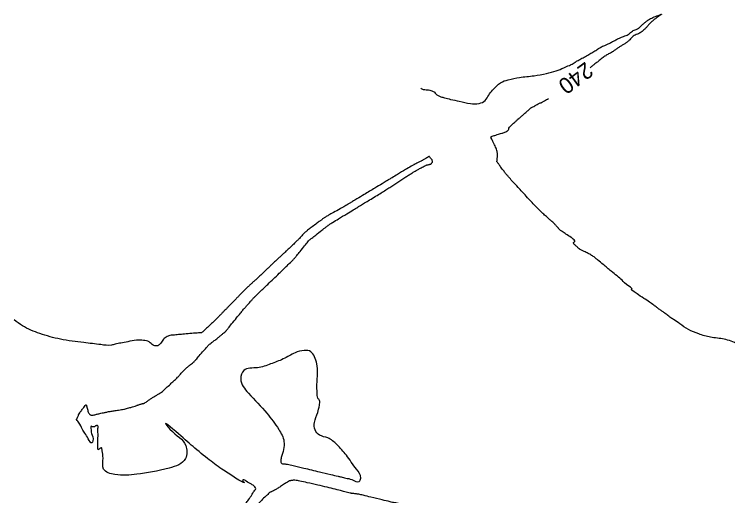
# Model space of a CAD drawing. Extents: x -478102 to -473059, y -1117705 to -1114104.
# Drawn here: x -477151.4 to -476973.3, y -1115105.7 to -1114985.6 of the extents above; entities that cross this region are included whole.
import ezdxf

# ---------------------------------------------------------------- set-up
doc = ezdxf.new("R2010")
doc.units = 0
for name, color, linetype in [('Vrstevnice_hlavni', 7, 'Continuous'), ('Vrstevnice_popis', 7, 'Continuous'), ('Vrstevnice_vedlejsi', 7, 'Continuous')]:
    doc.layers.add(name, color=color, linetype=linetype)

msp = doc.modelspace()

# ---------------------------------------------------------------- linework, layer by layer
at = {"layer": 'Vrstevnice_hlavni'}
for points in [[(-477049.979, -1115004.029), (-477049.673, -1115004.193), (-477048.26, -1115004.404), (-477047.204, -1115004.683), (-477046.505, -1115005.027), (-477046.164, -1115005.438), (-477045.639, -1115005.805), (-477044.929, -1115006.127), (-477044.034, -1115006.405), (-477042.508, -1115006.787), (-477040.351, -1115007.273), (-477037.562, -1115007.863), (-477035.407, -1115007.799), (-477033.886, -1115007.079), (-477033, -1115005.704), (-477032.062, -1115004.503), (-477031.073, -1115003.477), (-477030.034, -1115002.625), (-477028.119, -1115001.907), (-477025.328, -1115001.324), (-477021.663, -1115000.876), (-477018.599, -1115000.325), (-477016.138, -1114999.672), (-477014.278, -1114998.917), (-477012.873, -1114998.304), (-477011.923, -1114997.835), (-477011.428, -1114997.509), (-477010.705, -1114997.08), (-477009.754, -1114996.549), (-477008.574, -1114995.914), (-477007.491, -1114995.299), (-477006.505, -1114994.702), (-477005.616, -1114994.125), (-477004.874, -1114993.69), (-477004.28, -1114993.398), (-477003.833, -1114993.249), (-477003.188, -1114992.955), (-477002.345, -1114992.516), (-477001.305, -1114991.933), (-477000.403, -1114991.481), (-476999.64, -1114991.162), (-476999.016, -1114990.973), (-476998.464, -1114990.728), (-476997.985, -1114990.425), (-476997.579, -1114990.066), (-476997.143, -1114989.765), (-476996.676, -1114989.524), (-476996.178, -1114989.342), (-476995.627, -1114989.011), (-476995.023, -1114988.533), (-476994.365, -1114987.907), (-476993.741, -1114987.384), (-476993.153, -1114986.963), (-476992.599, -1114986.645), (-476992.009, -1114986.355), (-476991.383, -1114986.092), (-476990.719, -1114985.856), (-476990.255, -1114985.689), (-476989.991, -1114985.591), (-476989.925, -1114985.561), (-476989.901, -1114985.553), (-476989.919, -1114985.568), (-476989.977, -1114985.605), (-476990.02, -1114985.633), (-476990.048, -1114985.653), (-476990.061, -1114985.663), (-476990.326, -1114985.857), (-476990.841, -1114986.233), (-476991.608, -1114986.792), (-476992.308, -1114987.388), (-476992.94, -1114988.02), (-476993.504, -1114988.689), (-476994.025, -1114989.245), (-476994.503, -1114989.688), (-476994.937, -1114990.017), (-476995.402, -1114990.301), (-476995.899, -1114990.54), (-476996.428, -1114990.734), (-476996.92, -1114991.026), (-476997.375, -1114991.417), (-476997.795, -1114991.906), (-476998.298, -1114992.365), (-476998.884, -1114992.793), (-476999.553, -1114993.19), (-477000.214, -1114993.61), (-477000.867, -1114994.052), (-477001.512, -1114994.518), (-477002.106, -1114994.907), (-477002.649, -1114995.22), (-477003.142, -1114995.458), (-477003.814, -1114995.885), (-477004.665, -1114996.502)], [(-477004.665, -1114996.502), (-477005.695, -1114997.309), (-477006.489, -1114997.933), (-477007.047, -1114998.372), (-477007.691, -1114998.882)], [(-477017.894, -1115036.673), (-477018.831, -1115035.848), (-477019.673, -1115035.079), (-477020.422, -1115034.367), (-477021.076, -1115033.712), (-477022.168, -1115032.564), (-477023.697, -1115030.923), (-477025.662, -1115028.788), (-477027.122, -1115027.188), (-477028.074, -1115026.123), (-477028.52, -1115025.593), (-477029.034, -1115024.943), (-477029.617, -1115024.173), (-477030.269, -1115023.282), (-477030.708, -1115022.682), (-477030.934, -1115022.374), (-477030.946, -1115022.357), (-477030.928, -1115022.077), (-477030.878, -1115021.535), (-477030.797, -1115020.729), (-477030.934, -1115019.788), (-477031.286, -1115018.713), (-477031.856, -1115017.503), (-477032.238, -1115016.683), (-477032.433, -1115016.253), (-477032.44, -1115016.214), (-477032.443, -1115016.185), (-477032.441, -1115016.166), (-477032.435, -1115016.159), (-477032.431, -1115016.153), (-477032.428, -1115016.149), (-477032.426, -1115016.147), (-477032.373, -1115016.122), (-477032.267, -1115016.074), (-477032.11, -1115016.003), (-477031.64, -1115015.843), (-477030.858, -1115015.596), (-477029.763, -1115015.26), (-477028.959, -1115014.975), (-477028.444, -1115014.74), (-477028.219, -1115014.556), (-477028.06, -1115014.364), (-477027.968, -1115014.165), (-477027.943, -1115013.958), (-477027.674, -1115013.593), (-477027.161, -1115013.071), (-477026.405, -1115012.392), (-477025.889, -1115011.927), (-477025.616, -1115011.677), (-477025.583, -1115011.642), (-477025.534, -1115011.602), (-477025.469, -1115011.556), (-477025.387, -1115011.505), (-477025.033, -1115011.201), (-477024.407, -1115010.643), (-477023.509, -1115009.833), (-477022.858, -1115009.263), (-477022.455, -1115008.935), (-477022.299, -1115008.848), (-477021.991, -1115008.674), (-477021.533, -1115008.413), (-477020.923, -1115008.064), (-477020.468, -1115007.826), (-477020.167, -1115007.697), (-477020.021, -1115007.678), (-477019.883, -1115007.635), (-477019.754, -1115007.567), (-477019.633, -1115007.475), (-477019.398, -1115007.325), (-477019.047, -1115007.117), (-477018.115, -1115006.584)], [(-476873.251, -1115143.677), (-476873.507, -1115142.01), (-476873.554, -1115139.102), (-476873.522, -1115134.12), (-476873.41, -1115127.063), (-476873.808, -1115122.086), (-476874.717, -1115119.19), (-476876.136, -1115118.374), (-476877.354, -1115117.171), (-476878.371, -1115115.579), (-476879.185, -1115113.6), (-476882.364, -1115111.475), (-476887.908, -1115109.205), (-476895.815, -1115106.789), (-476902.242, -1115103.761), (-476907.186, -1115100.12), (-476910.649, -1115095.867), (-476913.66, -1115091.883), (-476916.218, -1115088.167), (-476918.324, -1115084.72), (-476919.725, -1115082.379), (-476920.421, -1115081.145), (-476920.412, -1115081.017), (-476920.426, -1115080.932), (-476920.462, -1115080.891), (-476920.521, -1115080.893), (-476920.576, -1115080.895), (-476920.627, -1115080.896), (-476920.674, -1115080.898), (-476921.736, -1115080.799), (-476923.814, -1115080.599), (-476926.907, -1115080.3), (-476932.302, -1115079.591), (-476940, -1115078.472), (-476950, -1115076.944), (-476957.876, -1115075.006), (-476963.629, -1115072.657), (-476967.259, -1115069.897), (-476970.802, -1115067.892), (-476974.259, -1115066.643), (-476977.631, -1115066.149), (-476980.601, -1115065.341), (-476983.17, -1115064.218), (-476985.338, -1115062.781), (-476986.878, -1115061.747), (-476987.79, -1115061.118), (-476988.074, -1115060.892), (-476988.478, -1115060.587), (-476989.003, -1115060.204), (-476989.648, -1115059.743), (-476990.332, -1115059.246), (-476991.055, -1115058.714), (-476991.817, -1115058.146), (-476992.891, -1115057.395), (-476994.277, -1115056.46), (-476995.976, -1115055.343), (-476997.039, -1115054.593), (-476997.464, -1115054.21), (-476997.254, -1115054.195), (-476998.009, -1115053.437), (-476999.729, -1115051.937), (-477002.416, -1115049.693), (-477004.444, -1115048.001), (-477005.814, -1115046.86), (-477006.527, -1115046.27), (-477007.324, -1115045.723), (-477008.206, -1115045.221), (-477009.173, -1115044.763), (-477009.833, -1115044.445), (-477010.186, -1115044.267), (-477010.232, -1115044.228), (-477010.318, -1115044.158), (-477010.443, -1115044.058), (-477010.608, -1115043.927), (-477010.866, -1115043.703), (-477011.219, -1115043.389), (-477011.666, -1115042.982), (-477011.859, -1115042.654), (-477011.796, -1115042.405), (-477011.479, -1115042.235), (-477011.695, -1115041.846), (-477012.445, -1115041.236), (-477013.729, -1115040.407), (-477014.642, -1115039.799), (-477015.184, -1115039.41), (-477015.355, -1115039.241), (-477015.476, -1115039.117), (-477015.545, -1115039.038), (-477015.564, -1115039.003), (-477015.672, -1115038.875), (-477015.869, -1115038.653), (-477016.157, -1115038.339), (-477016.405, -1115038.07), (-477016.615, -1115037.849), (-477016.786, -1115037.674), (-477017.213, -1115037.282), (-477017.894, -1115036.673)]]:
    msp.add_spline(points, degree=3, dxfattribs=at)
at = {"layer": 'Vrstevnice_vedlejsi'}
for points in [[(-477108.024, -1115073.453), (-477107.41, -1115072.982), (-477106.961, -1115072.629), (-477106.676, -1115072.395), (-477106.556, -1115072.278), (-477106.091, -1115071.757), (-477105.281, -1115070.832), (-477104.126, -1115069.502), (-477103.309, -1115068.574), (-477102.828, -1115068.046), (-477102.685, -1115067.92), (-477102.316, -1115067.626), (-477101.72, -1115067.165), (-477100.898, -1115066.537), (-477100.184, -1115065.97), (-477099.579, -1115065.464), (-477099.081, -1115065.02), (-477098.73, -1115064.701), (-477098.524, -1115064.509), (-477098.465, -1115064.444), (-477098.01, -1115063.889), (-477097.162, -1115062.844), (-477095.919, -1115061.311), (-477094.978, -1115060.158), (-477094.339, -1115059.385), (-477094.002, -1115058.992), (-477093.57, -1115058.494), (-477093.044, -1115057.889), (-477092.423, -1115057.178), (-477091.967, -1115056.663), (-477091.675, -1115056.343), (-477091.547, -1115056.218), (-477091.414, -1115056.093), (-477091.276, -1115055.968), (-477091.133, -1115055.843), (-477090.09, -1115054.841), (-477088.145, -1115052.963), (-477085.299, -1115050.207), (-477083.328, -1115048.299), (-477082.232, -1115047.238), (-477082.012, -1115047.025), (-477081.803, -1115046.81), (-477081.606, -1115046.593), (-477081.422, -1115046.376), (-477080.916, -1115045.76), (-477080.09, -1115044.745), (-477078.942, -1115043.332), (-477078.165, -1115042.381), (-477077.759, -1115041.889), (-477077.722, -1115041.859), (-477077.193, -1115041.444), (-477076.171, -1115040.644), (-477074.656, -1115039.459), (-477073.586, -1115038.623), (-477072.96, -1115038.136), (-477072.779, -1115037.999), (-477071.961, -1115037.49), (-477070.508, -1115036.61), (-477068.419, -1115035.359), (-477066.799, -1115034.381), (-477065.649, -1115033.675), (-477064.968, -1115033.243), (-477064.004, -1115032.647), (-477062.756, -1115031.889), (-477061.226, -1115030.967), (-477059.874, -1115030.136), (-477058.7, -1115029.396), (-477057.706, -1115028.747), (-477056.705, -1115028.092), (-477055.698, -1115027.432), (-477054.685, -1115026.767), (-477053.73, -1115026.157), (-477052.836, -1115025.601), (-477052, -1115025.101), (-477051.326, -1115024.7), (-477050.814, -1115024.399), (-477050.463, -1115024.197), (-477050.058, -1115023.975), (-477049.6, -1115023.733), (-477049.089, -1115023.47), (-477048.739, -1115023.29), (-477048.551, -1115023.192), (-477048.525, -1115023.177), (-477048.392, -1115023.144), (-477048.151, -1115023.091), (-477047.802, -1115023.02), (-477047.557, -1115022.962), (-477047.416, -1115022.917), (-477047.38, -1115022.886), (-477047.304, -1115022.801), (-477047.188, -1115022.663), (-477047.034, -1115022.472), (-477047.024, -1115022.224), (-477047.159, -1115021.92), (-477047.44, -1115021.559), (-477047.642, -1115021.3), (-477047.764, -1115021.143)], [(-477047.764, -1115021.143), (-477047.807, -1115021.087), (-477047.84, -1115021.051), (-477047.862, -1115021.035), (-477047.874, -1115021.038), (-477048.066, -1115021.148), (-477048.439, -1115021.365), (-477048.993, -1115021.689), (-477049.369, -1115021.906), (-477049.566, -1115022.018), (-477049.585, -1115022.024), (-477049.603, -1115022.032), (-477049.62, -1115022.044), (-477049.636, -1115022.059), (-477049.869, -1115022.179), (-477050.319, -1115022.405), (-477050.986, -1115022.735), (-477051.44, -1115022.961), (-477051.68, -1115023.08), (-477051.707, -1115023.094), (-477052.394, -1115023.504), (-477053.742, -1115024.308), (-477055.751, -1115025.507), (-477057.143, -1115026.339), (-477057.916, -1115026.803), (-477058.072, -1115026.899), (-477058.233, -1115027.001), (-477058.398, -1115027.108), (-477058.569, -1115027.221), (-477059.569, -1115027.831), (-477061.399, -1115028.936), (-477064.059, -1115030.537), (-477065.922, -1115031.657), (-477066.987, -1115032.295), (-477067.255, -1115032.451), (-477067.533, -1115032.618), (-477067.822, -1115032.796), (-477068.122, -1115032.984), (-477068.88, -1115033.421), (-477070.096, -1115034.105), (-477071.77, -1115035.038), (-477072.989, -1115035.726), (-477073.751, -1115036.168), (-477074.057, -1115036.365), (-477074.333, -1115036.554), (-477074.579, -1115036.736), (-477074.794, -1115036.91), (-477075.324, -1115037.31), (-477076.168, -1115037.936), (-477077.327, -1115038.79), (-477078.203, -1115039.464), (-477078.798, -1115039.959), (-477079.111, -1115040.275), (-477079.455, -1115040.634), (-477079.831, -1115041.038), (-477080.238, -1115041.485), (-477080.787, -1115042.043), (-477081.476, -1115042.712), (-477082.307, -1115043.493), (-477083.019, -1115044.159), (-477083.61, -1115044.71), (-477084.082, -1115045.147), (-477084.651, -1115045.674), (-477085.315, -1115046.29), (-477086.075, -1115046.995), (-477086.782, -1115047.662), (-477087.437, -1115048.292), (-477088.038, -1115048.885), (-477088.682, -1115049.509), (-477089.369, -1115050.164), (-477090.097, -1115050.851), (-477090.791, -1115051.495), (-477091.451, -1115052.094), (-477092.076, -1115052.649), (-477092.683, -1115053.204), (-477093.273, -1115053.758), (-477093.846, -1115054.312), (-477094.405, -1115054.864), (-477094.949, -1115055.416), (-477095.479, -1115055.966), (-477096.073, -1115056.582), (-477096.731, -1115057.264), (-477097.453, -1115058.011), (-477098.084, -1115058.661), (-477098.627, -1115059.215), (-477099.079, -1115059.673), (-477099.591, -1115060.191), (-477100.163, -1115060.77), (-477100.794, -1115061.411), (-477101.243, -1115061.866), (-477101.509, -1115062.137), (-477101.593, -1115062.222), (-477101.981, -1115062.587), (-477102.673, -1115063.234), (-477103.67, -1115064.162), (-477104.352, -1115064.774), (-477104.719, -1115065.07)], [(-477104.719, -1115065.07), (-477104.772, -1115065.05), (-477105.421, -1115065.088), (-477106.667, -1115065.183), (-477108.511, -1115065.336), (-477110.106, -1115065.477), (-477111.454, -1115065.605), (-477112.553, -1115065.721), (-477113.519, -1115066.142), (-477114.351, -1115066.867), (-477115.049, -1115067.896), (-477115.853, -1115068.319), (-477116.761, -1115068.135), (-477117.775, -1115067.344), (-477119.166, -1115066.938), (-477120.933, -1115066.918), (-477123.077, -1115067.283), (-477124.834, -1115067.608), (-477126.206, -1115067.891), (-477127.191, -1115068.133), (-477129.805, -1115068.007), (-477134.047, -1115067.513), (-477139.917, -1115066.65), (-477145.027, -1115065.24), (-477149.376, -1115063.284), (-477151.42, -1115061.854)], [(-477084.767, -1115096.166), (-477084.101, -1115092.168), (-477085.414, -1115089.159), (-477088.375, -1115085.141), (-477092.982, -1115080.113), (-477094.907, -1115076.543), (-477094.15, -1115074.431), (-477090.711, -1115073.778), (-477087.427, -1115072.83), (-477084.299, -1115071.587), (-477081.325, -1115070.05), (-477079.03, -1115069.446), (-477077.412, -1115069.774), (-477076.472, -1115071.036), (-477075.902, -1115072.82), (-477075.702, -1115075.127), (-477075.871, -1115077.957), (-477075.854, -1115080.036), (-477075.649, -1115081.363), (-477075.256, -1115081.94), (-477075.268, -1115083.139), (-477075.685, -1115084.961), (-477076.505, -1115087.406), (-477076.358, -1115089.277), (-477075.242, -1115090.575), (-477073.158, -1115091.299), (-477070.923, -1115092.964), (-477068.536, -1115095.569), (-477065.998, -1115099.114), (-477064.928, -1115101.316), (-477065.326, -1115102.175), (-477067.193, -1115101.689), (-477068.694, -1115101.308), (-477069.828, -1115101.031), (-477070.596, -1115100.857), (-477072.409, -1115100.429), (-477075.269, -1115099.746), (-477079.173, -1115098.808), (-477081.829, -1115098.176), (-477083.236, -1115097.849), (-477083.394, -1115097.828), (-477083.654, -1115097.801), (-477084.015, -1115097.767), (-477084.479, -1115097.728), (-477084.768, -1115097.532), (-477084.883, -1115097.181), (-477084.767, -1115096.166)], [(-477129.643, -1115093.662), (-477129.855, -1115093.807), (-477130.059, -1115093.953), (-477130.255, -1115094.099), (-477130.445, -1115094.246), (-477130.55, -1115093.657), (-477130.571, -1115092.334), (-477130.508, -1115090.275), (-477130.534, -1115088.901), (-477130.65, -1115088.214), (-477130.857, -1115088.211), (-477131.052, -1115088.259), (-477131.235, -1115088.355), (-477131.407, -1115088.501), (-477131.624, -1115088.556), (-477131.885, -1115088.52), (-477132.189, -1115088.393), (-477132.278, -1115088.939), (-477132.151, -1115090.158), (-477131.807, -1115092.05), (-477132.073, -1115092.497), (-477132.948, -1115091.498), (-477134.433, -1115089.053), (-477135.392, -1115087.379), (-477135.824, -1115086.476), (-477135.732, -1115086.343), (-477135.622, -1115086.14), (-477135.496, -1115085.867), (-477135.352, -1115085.524), (-477135.069, -1115085.043), (-477134.645, -1115084.425), (-477134.081, -1115083.669), (-477133.693, -1115083.193), (-477133.481, -1115082.995), (-477133.446, -1115083.075), (-477133.419, -1115083.139), (-477133.4, -1115083.187), (-477133.39, -1115083.217), (-477133.336, -1115083.429), (-477133.239, -1115083.824), (-477133.098, -1115084.4), (-477132.937, -1115084.867), (-477132.754, -1115085.224), (-477132.55, -1115085.472), (-477132.273, -1115085.607), (-477131.924, -1115085.629), (-477131.503, -1115085.538), (-477131.093, -1115085.446), (-477130.693, -1115085.354), (-477130.303, -1115085.261), (-477129.783, -1115085.141), (-477129.131, -1115084.995), (-477128.35, -1115084.823), (-477127.47, -1115084.655), (-477126.491, -1115084.493), (-477125.414, -1115084.335), (-477124.621, -1115084.217), (-477124.114, -1115084.138), (-477123.891, -1115084.098), (-477123.449, -1115083.985), (-477122.787, -1115083.8), (-477121.905, -1115083.541), (-477121.265, -1115083.345), (-477120.867, -1115083.213), (-477120.711, -1115083.143), (-477120.481, -1115083.058), (-477120.176, -1115082.956), (-477119.798, -1115082.837), (-477119.534, -1115082.756), (-477119.385, -1115082.712), (-477119.35, -1115082.705), (-477119.288, -1115082.693), (-477119.198, -1115082.677), (-477119.082, -1115082.657), (-477119.001, -1115082.642), (-477118.957, -1115082.632), (-477118.949, -1115082.628), (-477118.741, -1115082.484), (-477118.333, -1115082.199), (-477117.725, -1115081.775), (-477117.071, -1115081.344), (-477116.374, -1115080.908), (-477115.631, -1115080.466), (-477115.101, -1115080.147), (-477114.783, -1115079.952), (-477114.678, -1115079.88), (-477114.253, -1115079.504), (-477113.508, -1115078.823), (-477112.443, -1115077.838), (-477111.674, -1115077.129), (-477111.202, -1115076.694), (-477111.026, -1115076.535), (-477110.663, -1115076.156), (-477110.113, -1115075.558), (-477109.375, -1115074.741), (-477108.679, -1115074.039), (-477108.024, -1115073.453)], [(-477145.994, -1115130.93), (-477145.907, -1115130.949), (-477145.792, -1115130.975), (-477145.65, -1115131.008), (-477145.481, -1115131.047), (-477145.355, -1115131.153), (-477145.271, -1115131.326), (-477145.229, -1115131.567), (-477145.169, -1115131.745), (-477145.091, -1115131.861), (-477144.995, -1115131.914), (-477144.768, -1115132.33), (-477144.41, -1115133.109), (-477143.921, -1115134.25), (-477143.473, -1115135.123), (-477143.067, -1115135.728), (-477142.703, -1115136.064), (-477142.298, -1115136.403), (-477141.851, -1115136.742), (-477141.362, -1115137.084), (-477140.677, -1115137.524), (-477139.796, -1115138.061), (-477138.718, -1115138.696), (-477137.989, -1115139.121), (-477137.608, -1115139.337), (-477137.576, -1115139.344), (-477137.371, -1115138.849), (-477136.992, -1115137.853), (-477136.441, -1115136.356), (-477135.916, -1115135.328), (-477135.418, -1115134.771), (-477134.946, -1115134.683), (-477134.587, -1115134.579), (-477134.341, -1115134.46), (-477134.209, -1115134.324), (-477133.319, -1115134.179), (-477131.672, -1115134.026), (-477129.269, -1115133.863), (-477128.244, -1115133.003), (-477128.597, -1115131.444), (-477130.328, -1115129.187), (-477130.863, -1115127.236), (-477130.202, -1115125.591), (-477128.344, -1115124.252), (-477126.5, -1115123.02), (-477124.668, -1115121.895), (-477122.85, -1115120.877), (-477121.643, -1115120.158), (-477121.049, -1115119.737), (-477121.066, -1115119.615), (-477121.462, -1115119.154), (-477122.237, -1115118.356), (-477123.39, -1115117.219), (-477124.078, -1115116.277), (-477124.301, -1115115.53), (-477124.06, -1115114.978), (-477124.281, -1115113.735), (-477124.966, -1115111.8), (-477126.113, -1115109.174), (-477123.549, -1115107.946), (-477117.274, -1115108.116), (-477107.287, -1115109.684), (-477100.243, -1115110.346), (-477096.142, -1115110.101), (-477094.985, -1115108.95), (-477094.099, -1115108.048), (-477093.486, -1115107.396), (-477093.145, -1115106.994), (-477092.79, -1115106.515), (-477092.422, -1115105.958), (-477092.04, -1115105.325), (-477091.701, -1115104.783), (-477091.403, -1115104.332), (-477091.147, -1115103.973), (-477091.418, -1115103.476), (-477092.215, -1115102.842), (-477093.538, -1115102.069), (-477094.274, -1115101.745), (-477094.421, -1115101.87), (-477093.98, -1115102.444), (-477094.699, -1115102.169), (-477096.577, -1115101.045), (-477099.615, -1115099.073), (-477103.181, -1115096.412), (-477107.275, -1115093.063), (-477111.897, -1115089.024), (-477113.665, -1115087.698), (-477112.579, -1115089.085), (-477108.64, -1115093.184), (-477108.708, -1115096.426), (-477112.784, -1115098.812), (-477120.869, -1115100.342), (-477126.312, -1115100.433), (-477129.113, -1115099.086), (-477129.272, -1115096.301), (-477129.449, -1115094.493), (-477129.643, -1115093.662)], [(-477054.142, -1115124.985), (-477052.26, -1115123.757), (-477050.958, -1115122.904), (-477050.236, -1115122.428), (-477050.094, -1115122.328), (-477049.971, -1115122.239), (-477049.866, -1115122.163), (-477049.782, -1115122.098), (-477049.251, -1115121.664), (-477048.274, -1115120.86), (-477046.852, -1115119.687), (-477045.859, -1115118.869), (-477045.296, -1115118.408), (-477045.162, -1115118.303), (-477045.009, -1115118.174), (-477044.836, -1115118.019), (-477044.644, -1115117.84), (-477044.319, -1115117.576), (-477043.862, -1115117.229), (-477043.273, -1115116.796), (-477042.864, -1115116.472), (-477042.635, -1115116.256), (-477042.587, -1115116.148), (-477042.585, -1115116.018), (-477042.629, -1115115.867), (-477042.718, -1115115.693), (-477042.813, -1115115.552), (-477042.912, -1115115.443), (-477043.016, -1115115.367), (-477043.23, -1115115.233), (-477043.556, -1115115.039), (-477043.993, -1115114.787), (-477044.343, -1115114.605), (-477044.607, -1115114.493), (-477044.783, -1115114.452), (-477045.142, -1115114.353), (-477045.685, -1115114.195), (-477046.412, -1115113.98), (-477047.051, -1115113.734), (-477047.601, -1115113.457), (-477048.063, -1115113.149), (-477048.645, -1115112.465), (-477049.347, -1115111.404), (-477050.168, -1115109.966), (-477050.772, -1115108.966), (-477051.16, -1115108.404), (-477051.33, -1115108.278), (-477051.791, -1115108.174), (-477052.543, -1115108.091), (-477053.586, -1115108.028), (-477054.334, -1115107.97), (-477054.788, -1115107.917), (-477054.948, -1115107.868), (-477055.151, -1115107.804), (-477055.397, -1115107.724), (-477055.686, -1115107.63), (-477055.963, -1115107.559), (-477056.227, -1115107.512), (-477056.478, -1115107.488), (-477057.591, -1115107.241), (-477059.564, -1115106.769), (-477062.397, -1115106.073), (-477064.364, -1115105.599), (-477065.462, -1115105.346), (-477065.694, -1115105.314), (-477066.007, -1115105.275), (-477066.4, -1115105.227), (-477066.875, -1115105.17), (-477067.234, -1115105.122), (-477067.476, -1115105.081), (-477067.604, -1115105.048), (-477068.283, -1115104.875), (-477069.515, -1115104.562), (-477071.299, -1115104.11), (-477073.356, -1115103.609), (-477075.685, -1115103.06), (-477078.286, -1115102.462), (-477080.176, -1115102.066), (-477081.355, -1115101.87), (-477081.824, -1115101.874), (-477082.21, -1115101.904), (-477082.514, -1115101.96), (-477082.735, -1115102.04), (-477083.216, -1115102.31), (-477083.956, -1115102.769), (-477084.954, -1115103.416), (-477085.79, -1115103.938), (-477086.463, -1115104.333), (-477086.972, -1115104.602), (-477087.326, -1115104.773), (-477087.522, -1115104.846), (-477087.562, -1115104.822), (-477087.937, -1115105.152), (-477088.649, -1115105.835), (-477089.696, -1115106.872), (-477090.535, -1115107.703), (-477091.165, -1115108.327)]]:
    msp.add_spline(points, degree=3, dxfattribs=at)

# ---------------------------------------------------------------- texts
at = {"layer": 'Vrstevnice_popis'}
msp.add_text(' 240 ', height=4, rotation=216.46088, dxfattribs=at).set_placement((-477007.655, -1114996.369))

doc.saveas('drawing.dxf')
